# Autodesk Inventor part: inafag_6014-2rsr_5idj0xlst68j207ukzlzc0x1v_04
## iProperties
Shininess: 64.0
Angle Display Precision: 2
Document Length Units: 11269
Document Angle Units: 11279
Document Time Units: 11290
Document Mass Units: 11283
Document Length Units Precision: 3
Document Angle Units Precision: 2
Compacted: True
Created: 2008-08
Part Number: inafag_6014-2rsr_5idj0xlst68j207ukzlzc0x1v_04
Document SubType Name: Modeling
Designer: tpomodeler
Density: 0.0
Volumn: 0.0
Area: 0.0
PropertySet Name: Model Information
Control State: 0
Master: False
Checked Out: False
Author: tpomodeler
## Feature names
1. inafag_6014-2rsr_5idj0xlst68j207ukzlzc0x1v
